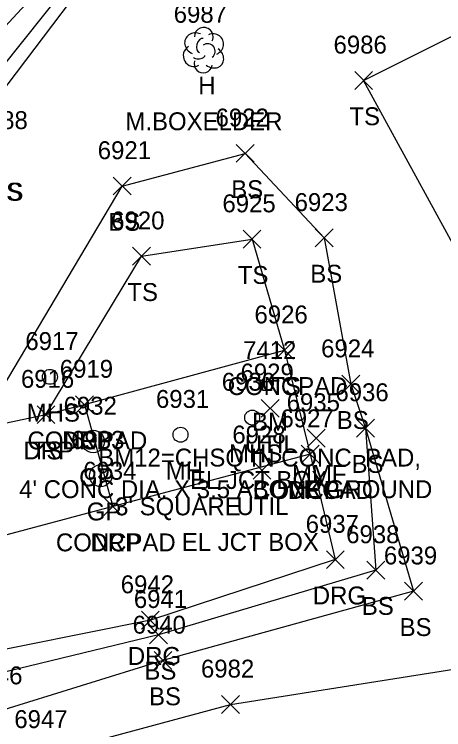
# Model space of a CAD drawing. Extents: x 1472233 to 1475777, y 540726 to 543442.
# Drawn here: x 1472698.2 to 1472746.2, y 541303.1 to 541383 of the extents above; entities that cross this region are included whole.
import ezdxf

# ---------------------------------------------------------------- set-up
doc = ezdxf.new("R2010")
doc.units = 0
for name, color, linetype in [('C_A', 7, 'Continuous'), ('C_C', 7, 'Continuous'), ('C_I', 7, 'Continuous'), ('CPBM', 7, 'Continuous'), ('L_A', 7, 'Continuous'), ('L_C', 7, 'Continuous'), ('L_I', 7, 'Continuous'), ('L_TIC', 7, 'Continuous'), ('LAWE', 7, 'Continuous'), ('LELB', 7, 'Continuous'), ('LS', 7, 'Continuous'), ('LTD', 7, 'Continuous'), ('R_A', 7, 'Continuous'), ('R_I', 7, 'Continuous'), ('R_TIC', 7, 'Continuous'), ('RDG', 7, 'Continuous'), ('RDP', 7, 'Continuous'), ('RGP', 7, 'Continuous'), ('U_A', 7, 'Continuous'), ('U_C', 7, 'Continuous'), ('U_I', 7, 'Continuous'), ('UDEFAULT', 7, 'Continuous'), ('USMH', 7, 'Continuous'), ('UUMH', 7, 'Continuous')]:
    doc.layers.add(name, color=color, linetype=linetype)

msp = doc.modelspace()

# ---------------------------------------------------------------- linework, layer by layer
at = {"layer": 'CPBM'}
for p, q in [((1472725.966, 541340.99), (1472725.966, 541341.99)), ((1472725.966, 541341.99), (1472726.966, 541341.99)), ((1472726.966, 541341.99), (1472726.966, 541340.99)), ((1472726.966, 541340.99), (1472725.966, 541340.99)), ((1472726.468, 541341.491), (1472726.468, 541341.491)), ((1472726.468, 541341.491), (1472726.468, 541341.491))]:
    msp.add_line(p, q, dxfattribs=at)
at = {"layer": 'L_TIC'}
for points in [[(1472736.242, 541374.612), (1472738.242, 541376.612)], [(1472738.242, 541374.612), (1472736.242, 541376.612)], [(1472723.01, 541366.466), (1472725.01, 541368.466)], [(1472725.01, 541366.466), (1472723.01, 541368.466)], [(1472709.287, 541362.82), (1472711.287, 541364.82)], [(1472711.287, 541362.82), (1472709.287, 541364.82)], [(1472723.777, 541356.885), (1472725.777, 541358.885)], [(1472725.777, 541356.885), (1472723.777, 541358.885)], [(1472731.84, 541357.022), (1472733.84, 541359.022)], [(1472733.84, 541357.022), (1472731.84, 541359.022)], [(1472711.445, 541354.977), (1472713.445, 541356.977)], [(1472713.445, 541354.977), (1472711.445, 541356.977)], [(1472727.411, 541344.475), (1472729.411, 541346.475)], [(1472729.411, 541344.475), (1472727.411, 541346.475)], [(1472727.411, 541344.475), (1472729.411, 541346.475)], [(1472729.411, 541344.475), (1472727.411, 541346.475)], [(1472734.8, 541340.686), (1472736.8, 541342.686)], [(1472736.8, 541340.686), (1472734.8, 541342.686)], [(1472705.054, 541338.404), (1472707.054, 541340.404)], [(1472707.054, 541338.404), (1472705.054, 541340.404)], [(1472700.766, 541337.284), (1472702.766, 541339.284)], [(1472702.766, 541337.284), (1472700.766, 541339.284)], [(1472736.449, 541335.783), (1472738.449, 541337.783)], [(1472738.449, 541335.783), (1472736.449, 541337.783)], [(1472736.449, 541335.783), (1472738.449, 541337.783)], [(1472738.449, 541335.783), (1472736.449, 541337.783)], [(1472730.951, 541334.668), (1472732.951, 541336.668)], [(1472732.951, 541334.668), (1472730.951, 541336.668)], [(1472730.256, 541332.87), (1472732.256, 541334.87)], [(1472732.256, 541332.87), (1472730.256, 541334.87)], [(1472708.232, 541327.017), (1472710.232, 541329.017)], [(1472710.232, 541327.017), (1472708.232, 541329.017)], [(1472737.598, 541319.922), (1472739.598, 541321.922)], [(1472739.598, 541319.922), (1472737.598, 541321.922)], [(1472741.819, 541317.557), (1472743.819, 541319.557)], [(1472743.819, 541317.557), (1472741.819, 541319.557)], [(1472713.319, 541312.691), (1472715.319, 541314.691)], [(1472715.319, 541312.691), (1472713.319, 541314.691)], [(1472713.833, 541309.824), (1472715.833, 541311.824)], [(1472715.833, 541309.824), (1472713.833, 541311.824)], [(1472721.381, 541304.916), (1472723.381, 541306.916)], [(1472723.381, 541304.916), (1472721.381, 541306.916)]]:
    msp.add_lwpolyline(points, dxfattribs=at)
at = {"layer": 'LAWE'}
for points in [[(1472778.929, 541490.66), (1472748.228, 541472.544), (1472728.371, 541462.26), (1472703.024, 541456.182), (1472699.775, 541442.826), (1472700.733, 541433.371), (1472715.471, 541431.594), (1472718.175, 541426.347), (1472716.653, 541420.135), (1472715.238, 541417.461), (1472710.253, 541415.257), (1472705.247, 541416.253), (1472696.443, 541412.999), (1472694.467, 541406.711), (1472701.72, 541395.349), (1472703.113, 541388.078), (1472688.036, 541371.772), (1472681.627, 541359.725), (1472680.599, 541356.394), (1472682.091, 541354.455)], [(1472782.301, 541487.238), (1472749.952, 541469.272), (1472729.675, 541458.762), (1472708.083, 541452.537), (1472701.662, 541441.745), (1472704.926, 541435.625), (1472717.433, 541433.686), (1472721.831, 541426.671), (1472718.921, 541419.502), (1472713.315, 541413.102), (1472709.745, 541413.542), (1472708.124, 541414.03), (1472705.342, 541413.794), (1472697.725, 541411.28), (1472697.349, 541408.314), (1472703.086, 541395.78), (1472705.871, 541388.45), (1472690.162, 541368.758), (1472683.844, 541359.568), (1472682.091, 541354.455)]]:
    msp.add_lwpolyline(points, dxfattribs=at)
at = {"layer": 'LELB'}
for points in [[(1472699.266, 541409.512), (1472705.366, 541396.52), (1472707.494, 541388.433), (1472691.453, 541367.272), (1472685.9, 541358.223), (1472685.45, 541352.662), (1472682.886, 541351.272), (1472677.168, 541353.025)], [(1472701.537, 541300.276), (1472722.381, 541305.916), (1472755.556, 541311.159), (1472754.666, 541333.295), (1472750.205, 541351.838), (1472737.242, 541375.612), (1472755.851, 541384.939), (1472791.788, 541385.485), (1472821.358, 541384.868), (1472858.925, 541384.478), (1472899.464, 541383.482), (1472951.044, 541384.205), (1472943.44, 541340.337), (1472927.567, 541299.156)], [(1472694.167, 541336.696), (1472710.287, 541363.82), (1472724.01, 541367.466), (1472732.84, 541358.022), (1472735.8, 541341.686), (1472737.449, 541336.783), (1472738.598, 541320.922), (1472714.319, 541313.691), (1472692.632, 541308.438), (1472692.612, 541304.716), (1472694.988, 541295.507), (1472702.177, 541269.109), (1472714.985, 541232.255), (1472725.569, 541201.652), (1472739.903, 541163.717), (1472759.74, 541112.631), (1472772.204, 541081.833), (1472792.335, 541035.431), (1472808.54, 541003.497), (1472813.847, 541002.676), (1472821.816, 541001.878), (1472830.877, 541001.108)], [(1472701.766, 541338.284), (1472712.445, 541355.977), (1472724.777, 541357.885), (1472728.411, 541345.475)], [(1472737.449, 541336.783), (1472742.819, 541318.557), (1472714.833, 541310.824), (1472696.554, 541305.163), (1472698.466, 541296.567), (1472707.518, 541271.263), (1472721.131, 541235.345)]]:
    msp.add_lwpolyline(points, dxfattribs=at)
at = {"layer": 'LS'}
msp.add_lwpolyline([(1472706.054, 541339.404), (1472728.411, 541345.475), (1472731.256, 541333.87), (1472709.232, 541328.017)], dxfattribs=at)
at = {"layer": 'LTD'}
msp.add_line((1472719.338, 541379.052), (1472719.338, 541379.052), dxfattribs=at)
msp.add_line((1472719.338, 541379.052), (1472719.338, 541379.052), dxfattribs=at)
msp.add_arc((1472719.385, 541380.486), 1.047, 335.52715, 180.95627, dxfattribs=at)
for centre, major_axis, ratio, start_param, end_param in [((1472718.546, 541379.718), (1.21, -0.512), 0.895232, 1.570796, 4.712389), ((1472720.379, 541379.635), (-1.141, -0.483), 0.949671, 1.570796, 4.712389), ((1472719.129, 541379.51), (-0.208, -0.792), 0.645439, 3.141593, 6.283185), ((1472718.255, 541378.343), (0.584, -1.042), 0.959034, 3.141593, 6.283185), ((1472719.838, 541378.885), (-0.5, 0.667), 0.989748, 3.141593, 6.283185), ((1472720.338, 541378.218), (-1.09, 0.792), 0.841452, 1.570796, 4.712389), ((1472718.88, 541378.302), (-0.625, -0.083), 0.423636, 0, 3.141593), ((1472719.338, 541377.552), (0.265, 1.061), 0.942809, 1.570796, 4.712389)]:
    msp.add_ellipse(centre, major_axis=major_axis, ratio=ratio, start_param=start_param, end_param=end_param, dxfattribs=at)
at = {"layer": 'R_TIC'}
for points in [[(1472705.054, 541338.404), (1472707.054, 541340.404)], [(1472707.054, 541338.404), (1472705.054, 541340.404)], [(1472700.766, 541337.284), (1472702.766, 541339.284)], [(1472702.766, 541337.284), (1472700.766, 541339.284)], [(1472730.256, 541332.87), (1472732.256, 541334.87)], [(1472732.256, 541332.87), (1472730.256, 541334.87)], [(1472708.232, 541327.017), (1472710.232, 541329.017)], [(1472710.232, 541327.017), (1472708.232, 541329.017)], [(1472733.076, 541321.087), (1472735.076, 541323.087)], [(1472735.076, 541321.087), (1472733.076, 541323.087)], [(1472712.421, 541314.332), (1472714.421, 541316.332)], [(1472714.421, 541314.332), (1472712.421, 541316.332)]]:
    msp.add_lwpolyline(points, dxfattribs=at)
at = {"layer": 'RDG'}
msp.add_lwpolyline([(1472731.256, 541333.87), (1472734.076, 541322.087), (1472713.421, 541315.332), (1472691.926, 541311.02), (1472688.466, 541308.958), (1472684.25, 541300.561)], dxfattribs=at)
at = {"layer": 'RDP'}
msp.add_lwpolyline([(1472670.649, 541335.937), (1472674.205, 541333.47), (1472677.483, 541332.846), (1472681.263, 541333.227), (1472694.167, 541336.696), (1472701.766, 541338.284), (1472706.054, 541339.404), (1472709.232, 541328.017), (1472684.805, 541321.495), (1472680.314, 541310.926)], dxfattribs=at)
at = {"layer": 'RGP'}
for p, q in [((1472707.04, 541335.283), (1472707.04, 541335.283)), ((1472707.881, 541331.471), (1472707.881, 541331.471))]:
    msp.add_line(p, q, dxfattribs=at)
for centre, radius in [((1472707.04, 541335.283), 1.25), ((1472707.04, 541335.283), 0.0833), ((1472707.881, 541331.471), 1.25), ((1472707.881, 541331.471), 0.0833)]:
    msp.add_circle(centre, radius, dxfattribs=at)
at = {"layer": 'UDEFAULT'}
for points in [[(1472725.808, 541337.986), (1472727.808, 541339.986)], [(1472727.808, 541337.986), (1472725.808, 541339.986)], [(1472724.887, 541331.063), (1472726.887, 541333.063)], [(1472726.887, 541331.063), (1472724.887, 541333.063)]]:
    msp.add_lwpolyline(points, dxfattribs=at)
at = {"layer": 'USMH'}
for p, q in [((1472702.201, 541342.504), (1472702.201, 541342.504)), ((1472703.035, 541342.504), (1472703.035, 541342.504)), ((1472724.795, 541337.958), (1472724.795, 541337.958)), ((1472725.628, 541337.958), (1472725.628, 541337.958))]:
    msp.add_line(p, q, dxfattribs=at)
for centre in [(1472702.201, 541342.504), (1472724.795, 541337.958)]:
    msp.add_circle(centre, 0.833, dxfattribs=at)
at = {"layer": 'UUMH'}
for p, q in [((1472716.789, 541336.04), (1472716.789, 541336.04)), ((1472717.623, 541336.04), (1472717.623, 541336.04))]:
    msp.add_line(p, q, dxfattribs=at)
msp.add_circle((1472716.789, 541336.04), 0.833, dxfattribs=at)

# ---------------------------------------------------------------- texts
at = {"layer": 'C_A'}
msp.add_text('BM', height=2, dxfattribs=at).set_placement((1472724.783, 541336.491))
at = {"layer": 'C_C'}
msp.add_text('BM12=CHSQ IN CONC. PAD,', height=2, dxfattribs=at).set_placement((1472707.602, 541332.491))
at = {"layer": 'C_I'}
msp.add_text('7412', height=2, dxfattribs=at).set_placement((1472723.775, 541344.491))
at = {"layer": 'L_A'}
for s, p in [('H', (1472718.771, 541374.052)), ('TS', (1472735.652, 541370.612)), ('CS', (1472695.532, 541362.179)), ('BS', (1472695.532, 541362.179)), ('BS', (1472722.451, 541362.466)), ('BS', (1472708.728, 541358.82)), ('TS', (1472723.186, 541352.885)), ('BS', (1472731.281, 541353.022)), ('TS', (1472710.854, 541350.977)), ('CONCPAD', (1472722.057, 541340.475)), ('TS', (1472726.821, 541340.475)), ('BS', (1472734.241, 541336.686)), ('CONCPAD', (1472699.699, 541334.404)), ('TS', (1472700.175, 541333.284)), ('BS', (1472735.89, 541331.783)), ('BS', (1472735.89, 541331.783)), ('MMF', (1472729.234, 541330.668)), ('CONCPAD', (1472724.902, 541328.87)), ('CONCPAD', (1472702.877, 541323.017)), ('BS', (1472737.039, 541315.922)), ('BS', (1472741.26, 541313.557)), ('BS', (1472712.76, 541308.691)), ('BS', (1472713.274, 541305.824))]:
    msp.add_text(s, height=2, dxfattribs=at).set_placement(p)
at = {"layer": 'L_C'}
msp.add_text('M.BOXELDER', height=2, dxfattribs=at).set_placement((1472710.637, 541370.052))
at = {"layer": 'L_I'}
for s, p in [('6987', (1472716.031, 541382.052)), ('6986', (1472733.88, 541378.612)), ('6888', (1472693.784, 541370.179)), ('6888', (1472693.784, 541370.179)), ('6922', (1472720.703, 541370.466)), ('6921', (1472707.547, 541366.82)), ('6925', (1472721.47, 541360.885)), ('6923', (1472729.533, 541361.022)), ('6920', (1472709.051, 541358.977)), ('6926', (1472725.049, 541348.475)), ('6926', (1472725.049, 541348.475)), ('6924', (1472732.493, 541344.686)), ('6919', (1472703.306, 541342.404)), ('6916', (1472698.971, 541341.284)), ('6936', (1472734.087, 541339.783)), ('6936', (1472734.087, 541339.783)), ('6935', (1472728.644, 541338.668)), ('6927', (1472727.949, 541336.87)), ('6934', (1472705.924, 541331.017)), ('6938', (1472735.291, 541323.922)), ('6939', (1472739.504, 541321.557)), ('6941', (1472711.579, 541316.691)), ('6940', (1472711.439, 541313.824)), ('6982', (1472719.074, 541308.916)), ('6946', (1472693.192, 541308.163)), ('6947', (1472698.23, 541303.276)), ('6947', (1472698.23, 541303.276))]:
    msp.add_text(s, height=2, dxfattribs=at).set_placement(p)
at = {"layer": 'R_A'}
for s, p in [('DRP', (1472703.542, 541334.404)), ('DRP', (1472699.254, 541333.284)), ('GP', (1472705.473, 541330.283)), ('DRG', (1472728.744, 541328.87)), ('GP', (1472706.314, 541326.471)), ('DRP', (1472706.72, 541323.017)), ('DRG', (1472731.564, 541317.087)), ('DRG', (1472710.91, 541310.332))]:
    msp.add_text(s, height=2, dxfattribs=at).set_placement(p)
at = {"layer": 'R_I'}
for s, p in [('6919', (1472703.306, 541342.404)), ('6916', (1472698.971, 541341.284)), ('6932', (1472703.733, 541338.283)), ('6927', (1472727.949, 541336.87)), ('6933', (1472704.574, 541334.471)), ('6934', (1472705.924, 541331.017)), ('6937', (1472730.769, 541325.087)), ('6942', (1472710.114, 541318.332))]:
    msp.add_text(s, height=2, dxfattribs=at).set_placement(p)
at = {"layer": 'U_A'}
for s, p in [('MHS', (1472699.619, 541337.504)), ('UTIL', (1472723.973, 541333.986)), ('MHS', (1472722.212, 541332.958)), ('MH', (1472715.151, 541331.04)), ('UTIL', (1472723.053, 541327.063))]:
    msp.add_text(s, height=2, dxfattribs=at).set_placement(p)
at = {"layer": 'U_C'}
for s, p in [('EL JCT BOX', (1472717.847, 541329.986)), ("4' CONC DIA. X 3.5 ABOVE GROUND", (1472698.771, 541328.958)), ("3' SQUARE", (1472709.482, 541327.04)), ('EL JCT BOX', (1472716.927, 541323.063))]:
    msp.add_text(s, height=2, dxfattribs=at).set_placement(p)
at = {"layer": 'U_I'}
for s, p in [('6917', (1472699.461, 541345.504)), ('6929', (1472723.493, 541341.986)), ('6930', (1472721.401, 541340.958)), ('6931', (1472714.049, 541339.04)), ('6928', (1472722.58, 541335.063))]:
    msp.add_text(s, height=2, dxfattribs=at).set_placement(p)

doc.saveas('drawing.dxf')
